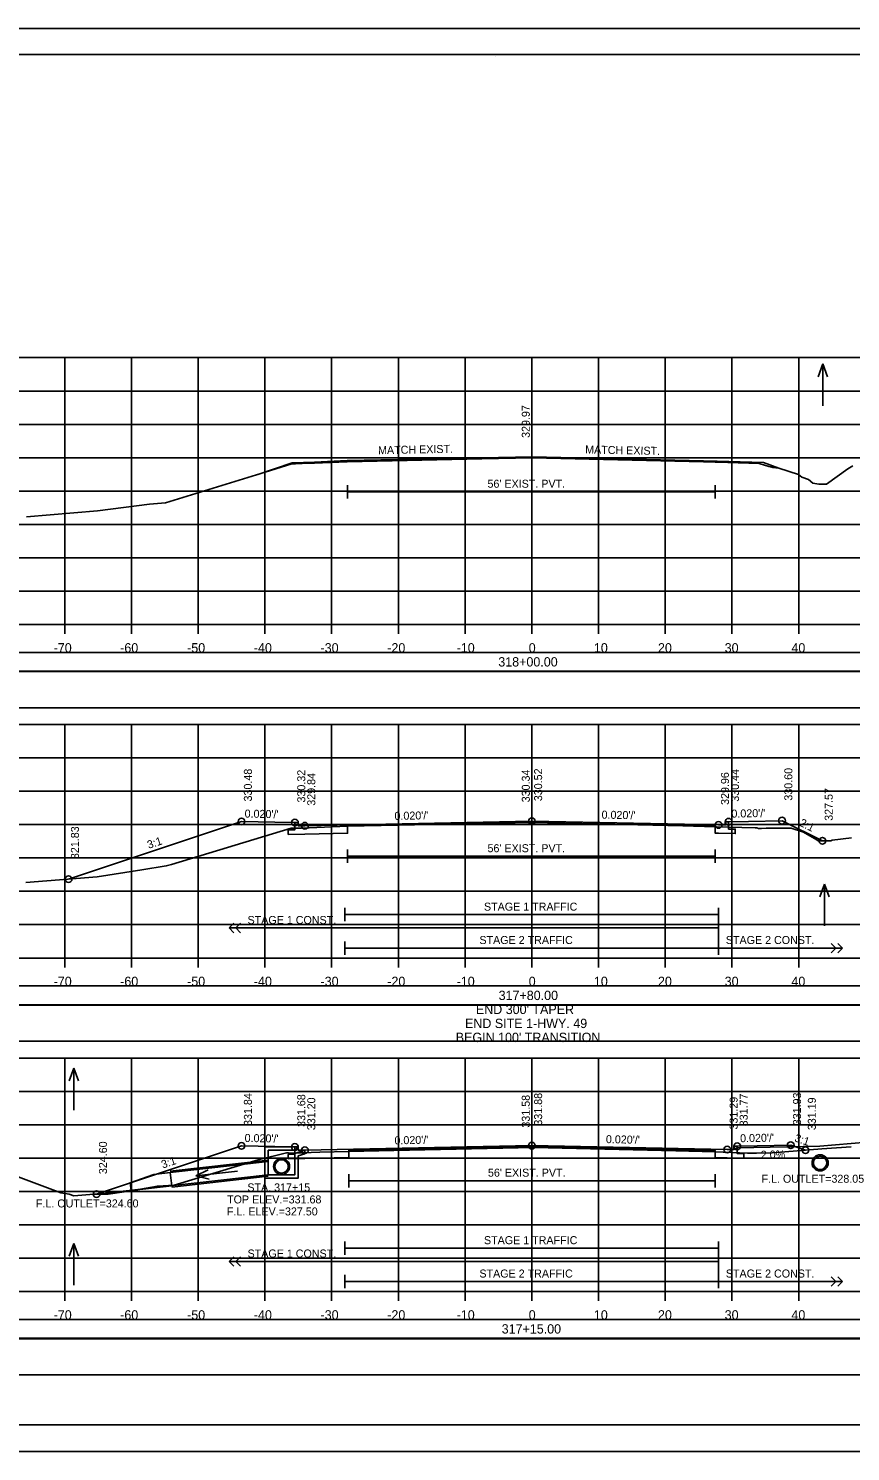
# Model space of a CAD drawing. Extents: x 1368122 to 1710785, y 373130 to 557566.
# Drawn here: x 1369280.1 to 1369403.3, y 375477 to 375690.4 of the extents above; entities that cross this region are included whole.
import ezdxf

# ---------------------------------------------------------------- set-up
doc = ezdxf.new("R2010")
doc.units = 0
for name, color, linetype in [('R_Alt Surface', 7, 'Continuous'), ('R_Axis', 7, 'Continuous'), ('R_Axis Annot', 7, 'Continuous'), ('R_Border', 7, 'Continuous'), ('R_Drive', 7, 'Continuous'), ('R_Exist Surface', 7, 'Continuous'), ('R_Fin Surface', 7, 'Continuous'), ('R_Grid', 7, 'Continuous'), ('R_No Plot', 7, 'Continuous'), ('R_Striping', 7, 'Continuous'), ('R_Water', 7, 'Continuous'), ('R_Water Annot', 7, 'Continuous'), ('R_Xsect Elev', 7, 'Continuous'), ('R_Xsect Slope', 7, 'Continuous')]:
    doc.layers.add(name, color=color, linetype=linetype)

msp = doc.modelspace()

# ---------------------------------------------------------------- linework, layer by layer
for points in [[(1369206.41, 375594.02), (1369504.71, 375594.02), (1369504.71, 375596.84), (1369206.41, 375596.84)], [(1369206.41, 375588.55), (1369504.71, 375588.55), (1369504.71, 375593.96), (1369206.41, 375593.96)], [(1369206.41, 375544.02), (1369504.71, 375544.02), (1369504.71, 375546.84), (1369206.41, 375546.84)], [(1369206.41, 375538.55), (1369504.71, 375538.55), (1369504.71, 375543.96), (1369206.41, 375543.96)], [(1369206.41, 375494.02), (1369504.71, 375494.02), (1369504.71, 375496.84), (1369206.41, 375496.84)], [(1369206.41, 375488.55), (1369504.71, 375488.55), (1369504.71, 375493.96), (1369206.41, 375493.96)]]:
    msp.add_lwpolyline(points, close=True)
at = {"layer": 'R_Alt Surface'}
for points in [[(1369327.95, 375621.93), (1369327.95, 375619.93)], [(1369383.05, 375621.93), (1369383.05, 375619.93)], [(1369327.95, 375620.93), (1369383.05, 375620.93)], [(1369385.06, 375571.46), (1369385.06, 375570.37), (1369386.06, 375570.35), (1369386.06, 375569.68), (1369383.56, 375569.73), (1369383.05, 375569.74), (1369383.05, 375570.82), (1369355.56, 375571.37), (1369327.95, 375570.82), (1369327.95, 375569.74), (1369321.56, 375569.61), (1369319.06, 375569.56), (1369319.06, 375570.23), (1369320.06, 375570.25), (1369320.06, 375571.34)], [(1369327.95, 375567.29), (1369327.95, 375565.29)], [(1369327.95, 375566.29), (1369383.05, 375566.29)], [(1369383.05, 375567.29), (1369383.05, 375565.29)], [(1369386.36, 375522.8), (1369386.36, 375521.71), (1369387.36, 375521.69), (1369387.36, 375521.02), (1369384.86, 375521.07), (1369383.02, 375521.1), (1369383.02, 375522.18), (1369355.56, 375522.73), (1369328.13, 375522.19), (1369328.13, 375521.11), (1369321.56, 375520.97), (1369319.06, 375520.92), (1369319.06, 375521.59), (1369320.06, 375521.61), (1369320.06, 375522.7)], [(1369328.13, 375518.65), (1369328.13, 375516.65)], [(1369328.13, 375517.65), (1369383.02, 375517.65)], [(1369383.02, 375518.65), (1369383.02, 375516.65)]]:
    msp.add_lwpolyline(points, dxfattribs=at)
at = {"layer": 'R_Axis'}
for p, q in [((1369205.56, 375601.03), (1369505.56, 375601.03)), ((1369285.56, 375599.63), (1369285.56, 375601.03)), ((1369295.56, 375599.63), (1369295.56, 375601.03)), ((1369305.56, 375599.63), (1369305.56, 375601.03)), ((1369315.56, 375599.63), (1369315.56, 375601.03)), ((1369325.56, 375599.63), (1369325.56, 375601.03)), ((1369335.56, 375599.63), (1369335.56, 375601.03)), ((1369345.56, 375599.63), (1369345.56, 375601.03)), ((1369355.56, 375599.63), (1369355.56, 375601.03)), ((1369365.56, 375599.63), (1369365.56, 375601.03)), ((1369375.56, 375599.63), (1369375.56, 375601.03)), ((1369385.56, 375599.63), (1369385.56, 375601.03)), ((1369395.56, 375599.63), (1369395.56, 375601.03)), ((1369205.56, 375551.03), (1369505.56, 375551.03)), ((1369285.56, 375549.63), (1369285.56, 375551.03)), ((1369295.56, 375549.63), (1369295.56, 375551.03)), ((1369305.56, 375549.63), (1369305.56, 375551.03)), ((1369315.56, 375549.63), (1369315.56, 375551.03)), ((1369325.56, 375549.63), (1369325.56, 375551.03)), ((1369335.56, 375549.63), (1369335.56, 375551.03)), ((1369345.56, 375549.63), (1369345.56, 375551.03)), ((1369355.56, 375549.63), (1369355.56, 375551.03)), ((1369365.56, 375549.63), (1369365.56, 375551.03)), ((1369375.56, 375549.63), (1369375.56, 375551.03)), ((1369385.56, 375549.63), (1369385.56, 375551.03)), ((1369395.56, 375549.63), (1369395.56, 375551.03)), ((1369205.56, 375501.03), (1369505.56, 375501.03)), ((1369285.56, 375499.63), (1369285.56, 375501.03)), ((1369295.56, 375499.63), (1369295.56, 375501.03)), ((1369305.56, 375499.63), (1369305.56, 375501.03)), ((1369315.56, 375499.63), (1369315.56, 375501.03)), ((1369325.56, 375499.63), (1369325.56, 375501.03)), ((1369335.56, 375499.63), (1369335.56, 375501.03)), ((1369345.56, 375499.63), (1369345.56, 375501.03)), ((1369355.56, 375499.63), (1369355.56, 375501.03)), ((1369365.56, 375499.63), (1369365.56, 375501.03)), ((1369375.56, 375499.63), (1369375.56, 375501.03)), ((1369385.56, 375499.63), (1369385.56, 375501.03)), ((1369395.56, 375499.63), (1369395.56, 375501.03))]:
    msp.add_line(p, q, dxfattribs=at)
at = {"layer": 'R_Border'}
for p, q in [((1369197.56, 375686.49), (1369513.74, 375686.49)), ((1369350.08, 375686.23), (1369350.08, 375686.23)), ((1369350.08, 375686.23), (1369350.08, 375686.23)), ((1369513.74, 375481.03), (1369197.56, 375481.03))]:
    msp.add_line(p, q, dxfattribs=at)
at = {"layer": 'R_Drive'}
for p, q in [((1369415.53, 375524.31), (1369398.74, 375522.8)), ((1369385.86, 375522.3), (1369386.36, 375522.55)), ((1369386.36, 375522.55), (1369398.74, 375522.8))]:
    msp.add_line(p, q, dxfattribs=at)
at = {"layer": 'R_Exist Surface'}
for points in [[(1369279.85, 375617.18), (1369290.45, 375618.07), (1369298.25, 375619.05), (1369300.66, 375619.29), (1369315.6, 375623.88), (1369319.62, 375625.13), (1369320.16, 375625.13), (1369321.14, 375625.14), (1369323, 375625.21), (1369327.91, 375625.42), (1369348.09, 375625.85), (1369355.61, 375626), (1369381.31, 375625.41), (1369383.02, 375625.36), (1369383.33, 375625.36), (1369389.66, 375625.16), (1369391.09, 375624.71), (1369391.33, 375624.64), (1369391.67, 375624.56), (1369392.6, 375624.48), (1369395.55, 375623.53), (1369396.04, 375623.14), (1369397.03, 375622.79), (1369397.69, 375622.23), (1369398.6, 375622.07), (1369399.71, 375622.06), (1369402.94, 375624.36), (1369403.68, 375624.81)], [(1369279.73, 375562.33), (1369290.4, 375563.22), (1369297.13, 375564.25), (1369300.78, 375564.83), (1369301.56, 375565.06), (1369319.52, 375570.52), (1369320.75, 375570.52), (1369321.05, 375570.52), (1369322.21, 375570.57), (1369327.95, 375570.79), (1369351.25, 375571.28), (1369355.69, 375571.37), (1369378.2, 375570.83), (1369383.05, 375570.71), (1369389.04, 375570.56), (1369389.28, 375570.55), (1369389.53, 375570.47), (1369389.64, 375570.46), (1369389.99, 375570.46), (1369390.67, 375570.51), (1369394.44, 375570.49), (1369396.3, 375569.92), (1369398.28, 375568.75), (1369398.46, 375568.61), (1369398.51, 375568.61), (1369400.36, 375568.58), (1369400.58, 375568.68), (1369403.5, 375569.04)], [(1369276.18, 375519.14), (1369284.97, 375515.83), (1369286.24, 375515.61), (1369286.93, 375515.38), (1369289.94, 375515.63), (1369292.05, 375515.61), (1369296.53, 375516.29), (1369296.93, 375516.4), (1369299.46, 375516.84), (1369299.47, 375516.84), (1369301.96, 375516.99), (1369314.55, 375520.78), (1369318.8, 375521.84), (1369319.11, 375521.83), (1369319.9, 375521.79), (1369323.81, 375521.9), (1369328.13, 375522.03), (1369334.87, 375522.17), (1369355.85, 375522.61), (1369377.17, 375522.1), (1369383.02, 375521.96), (1369387.87, 375521.79), (1369389.26, 375521.76), (1369391.6, 375521.82), (1369393.49, 375521.99), (1369399.01, 375522.4), (1369403.42, 375522.73)]]:
    msp.add_lwpolyline(points, dxfattribs=at)
at = {"layer": 'R_Fin Surface'}
for p, q in [((1369319.64, 375625.25), (1369314.49, 375623.54)), ((1369390.3, 375625.31), (1369392.6, 375624.48))]:
    msp.add_line(p, q, dxfattribs=at)
for points in [[(1369319.64, 375625.25), (1369323, 375625.38), (1369327.91, 375625.59), (1369348.09, 375626.02), (1369355.61, 375626.17), (1369381.31, 375625.58), (1369383.02, 375625.53), (1369383.33, 375625.53), (1369390.3, 375625.31)], [(1369286.14, 375562.86), (1369312.06, 375571.5), (1369317.06, 375571.4), (1369320.06, 375571.34), (1369320.56, 375571.34), (1369320.56, 375570.84), (1369321.56, 375570.86), (1369355.56, 375571.54), (1369383.56, 375570.98), (1369384.56, 375570.96), (1369384.56, 375571.46), (1369385.06, 375571.46), (1369388.06, 375571.52), (1369393.06, 375571.62), (1369399.11, 375568.6)], [(1369290.34, 375515.63), (1369312.06, 375522.86), (1369317.06, 375522.76), (1369320.06, 375522.7), (1369320.56, 375522.7), (1369320.56, 375522.2), (1369321.56, 375522.22), (1369355.56, 375522.9), (1369384.86, 375522.32), (1369385.86, 375522.3), (1369385.86, 375522.8), (1369386.36, 375522.8), (1369389.36, 375522.86), (1369394.36, 375522.96), (1369396.58, 375522.22)]]:
    msp.add_lwpolyline(points, dxfattribs=at)
at = {"layer": 'R_Grid'}
for p, q in [((1369205.56, 375641.03), (1369505.56, 375641.03)), ((1369285.56, 375601.03), (1369285.56, 375641.03)), ((1369295.56, 375601.03), (1369295.56, 375641.03)), ((1369305.56, 375601.03), (1369305.56, 375641.03)), ((1369315.56, 375601.03), (1369315.56, 375641.03)), ((1369325.56, 375601.03), (1369325.56, 375641.03)), ((1369335.56, 375601.03), (1369335.56, 375641.03)), ((1369345.56, 375601.03), (1369345.56, 375641.03)), ((1369355.56, 375601.03), (1369355.56, 375641.03)), ((1369365.56, 375601.03), (1369365.56, 375641.03)), ((1369375.56, 375601.03), (1369375.56, 375641.03)), ((1369385.56, 375601.03), (1369385.56, 375641.03)), ((1369395.56, 375601.03), (1369395.56, 375641.03)), ((1369205.56, 375636.03), (1369505.56, 375636.03)), ((1369205.56, 375631.03), (1369505.56, 375631.03)), ((1369205.56, 375626.03), (1369505.56, 375626.03)), ((1369205.56, 375621.03), (1369505.56, 375621.03)), ((1369205.56, 375616.03), (1369505.56, 375616.03)), ((1369205.56, 375611.03), (1369505.56, 375611.03)), ((1369205.56, 375606.03), (1369505.56, 375606.03)), ((1369205.56, 375601.03), (1369505.56, 375601.03)), ((1369205.56, 375586.03), (1369505.56, 375586.03)), ((1369285.56, 375551.03), (1369285.56, 375586.03)), ((1369295.56, 375551.03), (1369295.56, 375586.03)), ((1369305.56, 375551.03), (1369305.56, 375586.03)), ((1369315.56, 375551.03), (1369315.56, 375586.03)), ((1369325.56, 375551.03), (1369325.56, 375586.03)), ((1369335.56, 375551.03), (1369335.56, 375586.03)), ((1369345.56, 375551.03), (1369345.56, 375586.03)), ((1369355.56, 375551.03), (1369355.56, 375586.03)), ((1369365.56, 375551.03), (1369365.56, 375586.03)), ((1369375.56, 375551.03), (1369375.56, 375586.03)), ((1369385.56, 375551.03), (1369385.56, 375586.03)), ((1369395.56, 375551.03), (1369395.56, 375586.03)), ((1369205.56, 375581.03), (1369505.56, 375581.03)), ((1369205.56, 375576.03), (1369505.56, 375576.03)), ((1369205.56, 375571.03), (1369505.56, 375571.03)), ((1369205.56, 375566.03), (1369505.56, 375566.03)), ((1369205.56, 375561.03), (1369505.56, 375561.03)), ((1369205.56, 375556.03), (1369505.56, 375556.03)), ((1369205.56, 375551.03), (1369505.56, 375551.03)), ((1369205.56, 375536.03), (1369505.56, 375536.03)), ((1369285.56, 375501.03), (1369285.56, 375536.03)), ((1369295.56, 375501.03), (1369295.56, 375536.03)), ((1369305.56, 375501.03), (1369305.56, 375536.03)), ((1369315.56, 375501.03), (1369315.56, 375536.03)), ((1369325.56, 375501.03), (1369325.56, 375536.03)), ((1369335.56, 375501.03), (1369335.56, 375536.03)), ((1369345.56, 375501.03), (1369345.56, 375536.03)), ((1369355.56, 375501.03), (1369355.56, 375536.03)), ((1369365.56, 375501.03), (1369365.56, 375536.03)), ((1369375.56, 375501.03), (1369375.56, 375536.03)), ((1369385.56, 375501.03), (1369385.56, 375536.03)), ((1369395.56, 375501.03), (1369395.56, 375536.03)), ((1369205.56, 375531.03), (1369505.56, 375531.03)), ((1369205.56, 375526.03), (1369505.56, 375526.03)), ((1369205.56, 375521.03), (1369505.56, 375521.03)), ((1369205.56, 375516.03), (1369505.56, 375516.03)), ((1369205.56, 375511.03), (1369505.56, 375511.03)), ((1369205.56, 375506.03), (1369505.56, 375506.03)), ((1369205.56, 375501.03), (1369505.56, 375501.03))]:
    msp.add_line(p, q, dxfattribs=at)
at = {"layer": 'R_No Plot'}
for p, q in [((1369185.16, 375690.38), (1369518.49, 375690.38)), ((1369316.06, 375520.74), (1369301.35, 375519.08)), ((1369316.06, 375518.32), (1369301.62, 375516.69)), ((1369185.16, 375477.05), (1369518.49, 375477.05))]:
    msp.add_line(p, q, dxfattribs=at)
for points in [[(1369185.15, 375690.38), (1369518.49, 375690.38), (1369518.49, 375477.04), (1369185.15, 375477.04)], [(1369431.48, 375686.49), (1369451.1, 375686.49), (1369451.1, 375676.61), (1369467.21, 375676.61), (1369490.41, 375676.61), (1369490.53, 375648.45), (1369513.74, 375648.45), (1369513.74, 375481.03), (1369197.56, 375481.03), (1369197.56, 375686.49)]]:
    msp.add_lwpolyline(points, close=True, dxfattribs=at)
for centre, radius in [((1369312.06, 375571.5), 0.5), ((1369320.06, 375571.34), 0.5), ((1369321.56, 375570.86), 0.5), ((1369355.56, 375571.54), 0.5), ((1369383.56, 375570.98), 0.5), ((1369385.06, 375571.46), 0.5), ((1369393.06, 375571.62), 0.5), ((1369399.11, 375568.6), 0.5), ((1369286.14, 375562.86), 0.5), ((1369312.06, 375522.86), 0.5), ((1369355.56, 375522.9), 0.5), ((1369386.36, 375522.8), 0.5), ((1369394.36, 375522.96), 0.5), ((1369320.06, 375522.7), 0.5), ((1369321.56, 375522.22), 0.5), ((1369384.86, 375522.32), 0.5), ((1369396.58, 375522.22), 0.5), ((1369398.77, 375520.32), 1.21), ((1369318.06, 375519.78), 1.21), ((1369290.34, 375515.63), 0.5)]:
    msp.add_circle(centre, radius, dxfattribs=at)
at = {"layer": 'R_Striping'}
for p, q in [((1369310.2, 375555.53), (1369310.91, 375556.23)), ((1369310.91, 375554.82), (1369310.2, 375555.53)), ((1369311.2, 375555.53), (1369311.91, 375556.23)), ((1369311.91, 375554.82), (1369311.2, 375555.53)), ((1369401.11, 375552.53), (1369400.41, 375553.23)), ((1369402.11, 375552.53), (1369401.41, 375553.23)), ((1369402.11, 375552.53), (1369383.56, 375552.53)), ((1369400.41, 375551.82), (1369401.11, 375552.53)), ((1369401.41, 375551.82), (1369402.11, 375552.53)), ((1369310.2, 375505.53), (1369310.91, 375506.23)), ((1369311.2, 375505.53), (1369311.91, 375506.23)), ((1369310.91, 375504.82), (1369310.2, 375505.53)), ((1369311.91, 375504.82), (1369311.2, 375505.53)), ((1369402.11, 375502.53), (1369383.56, 375502.53)), ((1369401.11, 375502.53), (1369400.41, 375503.23)), ((1369400.41, 375501.82), (1369401.11, 375502.53)), ((1369402.11, 375502.53), (1369401.41, 375503.23)), ((1369401.41, 375501.82), (1369402.11, 375502.53))]:
    msp.add_line(p, q, dxfattribs=at)
for points in [[(1369327.56, 375558.53), (1369327.56, 375556.53)], [(1369327.56, 375557.53), (1369383.56, 375557.53)], [(1369383.56, 375558.53), (1369383.56, 375551.53)], [(1369383.56, 375555.53), (1369310.2, 375555.53)], [(1369327.56, 375553.53), (1369327.56, 375551.53)], [(1369327.56, 375552.53), (1369383.56, 375552.53)], [(1369327.56, 375508.53), (1369327.56, 375506.53)], [(1369383.56, 375508.53), (1369383.56, 375501.53)], [(1369327.56, 375507.53), (1369383.56, 375507.53)], [(1369383.56, 375505.53), (1369310.2, 375505.53)], [(1369327.56, 375503.53), (1369327.56, 375501.53)], [(1369327.56, 375502.53), (1369383.56, 375502.53)]]:
    msp.add_lwpolyline(points, dxfattribs=at)
at = {"layer": 'R_Water'}
for p, q in [((1369315.56, 375522.7), (1369320.31, 375522.7)), ((1369315.56, 375521.2), (1369315.56, 375522.7)), ((1369316.06, 375521.2), (1369316.06, 375522.2)), ((1369316.06, 375522.2), (1369320.06, 375522.2)), ((1369320.39, 375522.54), (1369320.06, 375522.2)), ((1369321.56, 375522.22), (1369320.06, 375521.7)), ((1369320.06, 375521.2), (1369320.06, 375521.7)), ((1369320.39, 375522.54), (1369320.31, 375522.7)), ((1369321.56, 375521.69), (1369320.56, 375521.35)), ((1369320.56, 375521.2), (1369320.56, 375521.35)), ((1369316.06, 375520.53), (1369301.38, 375518.87)), ((1369316.06, 375518.53), (1369290.34, 375515.63))]:
    msp.add_line(p, q, dxfattribs=at)
for points in [[(1369320.56, 375521.2), (1369320.56, 375518.03), (1369318.06, 375518.03), (1369315.56, 375518.03), (1369315.56, 375521.2)], [(1369320.06, 375521.2), (1369320.06, 375518.53), (1369318.06, 375518.53), (1369316.06, 375518.53), (1369316.06, 375521.2)], [(1369321.56, 375521.69), (1369321.56, 375522.22)]]:
    msp.add_lwpolyline(points, dxfattribs=at)
msp.add_lwpolyline([(1369301.38, 375518.87), (1369301.6, 375516.88), (1369295.52, 375516.2), (1369295.39, 375517.31), (1369298.89, 375518.59)], close=True, dxfattribs=at)
for centre in [(1369398.77, 375520.32), (1369318.06, 375519.78)]:
    msp.add_circle(centre, 1, dxfattribs=at)
at = {"layer": 'R_Water Annot'}
for p, q in [((1369399.16, 375640.09), (1369398.46, 375638.17)), ((1369399.16, 375633.81), (1369399.16, 375640.09)), ((1369399.16, 375640.09), (1369399.86, 375638.17)), ((1369399.44, 375562.12), (1369398.74, 375560.19)), ((1369399.44, 375555.83), (1369399.44, 375562.12)), ((1369399.44, 375562.12), (1369400.14, 375560.19)), ((1369286.93, 375534.52), (1369286.23, 375532.6)), ((1369286.93, 375528.24), (1369286.93, 375534.52)), ((1369286.93, 375534.52), (1369287.63, 375532.6)), ((1369305.22, 375518.36), (1369307.06, 375519.27)), ((1369311.47, 375519.06), (1369305.22, 375518.36)), ((1369305.22, 375518.36), (1369307.21, 375517.88)), ((1369286.93, 375508.25), (1369286.23, 375506.33)), ((1369286.93, 375501.97), (1369286.93, 375508.25)), ((1369286.93, 375508.25), (1369287.63, 375506.33))]:
    msp.add_line(p, q, dxfattribs=at)
at = {"layer": 'R_Xsect Elev'}
for p, q in [((1369355.56, 375626), (1369355.56, 375636)), ((1369355.56, 375571.37), (1369355.56, 375581.37)), ((1369355.56, 375522.6), (1369355.56, 375532.6))]:
    msp.add_line(p, q, dxfattribs=at)

# ---------------------------------------------------------------- texts
at = {"layer": 'R_Axis Annot'}
for s, p in [('-70', (1369283.9, 375596.83)), ('-60', (1369293.87, 375596.83)), ('-50', (1369303.9, 375596.83)), ('-40', (1369313.9, 375596.83)), ('-30', (1369323.9, 375596.83)), ('-20', (1369333.9, 375596.83)), ('-10', (1369344.3, 375596.83)), ('0', (1369355.1, 375596.83)), ('10', (1369364.87, 375596.83)), ('20', (1369374.47, 375596.83)), ('30', (1369384.47, 375596.83)), ('40', (1369394.47, 375596.83)), ('318+00.00', (1369350.54, 375594.73)), ('-70', (1369283.9, 375546.83)), ('-60', (1369293.87, 375546.83)), ('-50', (1369303.9, 375546.83)), ('-40', (1369313.9, 375546.83)), ('-30', (1369323.9, 375546.83)), ('-20', (1369333.9, 375546.83)), ('-10', (1369344.3, 375546.83)), ('0', (1369355.1, 375546.83)), ('10', (1369364.87, 375546.83)), ('20', (1369374.47, 375546.83)), ('30', (1369384.47, 375546.83)), ('40', (1369394.47, 375546.83)), ('317+80.00', (1369350.59, 375544.73)), ("END 300' TAPER", (1369347.18, 375542.63)), ('END SITE 1-HWY. 49', (1369345.55, 375540.53)), ("BEGIN 100' TRANSITION", (1369344.16, 375538.43)), ('-70', (1369283.9, 375496.83)), ('-60', (1369293.87, 375496.83)), ('-50', (1369303.9, 375496.83)), ('-40', (1369313.9, 375496.83)), ('-30', (1369323.9, 375496.83)), ('-20', (1369333.9, 375496.83)), ('-10', (1369344.3, 375496.83)), ('0', (1369355.1, 375496.83)), ('10', (1369364.87, 375496.83)), ('20', (1369374.47, 375496.83)), ('30', (1369384.47, 375496.83)), ('40', (1369394.47, 375496.83)), ('317+15.00', (1369351.05, 375494.73))]:
    msp.add_text(s, height=1.4, dxfattribs=at).set_placement(p)
at = {"layer": 'R_Striping'}
for s, p in [('STAGE 1 TRAFFIC', (1369348.39, 375558.13)), ('STAGE 1 CONST.', (1369312.96, 375556.13)), ('STAGE 2 TRAFFIC', (1369347.71, 375553.13)), ('STAGE 2 CONST.', (1369384.64, 375553.13)), ('STAGE 1 TRAFFIC', (1369348.39, 375508.13)), ('STAGE 1 CONST.', (1369312.96, 375506.13)), ('STAGE 2 TRAFFIC', (1369347.71, 375503.13)), ('STAGE 2 CONST.', (1369384.64, 375503.13))]:
    msp.add_text(s, height=1.2, dxfattribs=at).set_placement(p)
at = {"layer": 'R_Water'}
for p in [(1369348.92, 375621.53), (1369348.92, 375566.89), (1369348.99, 375518.25)]:
    msp.add_text("56' EXIST. PVT.", height=1.2, dxfattribs=at).set_placement(p)
at = {"layer": 'R_Water Annot'}
for s, p in [('STA. 317+15', (1369312.93, 375516.04)), ('F.L. OUTLET=328.05', (1369389.99, 375517.34)), ('F.L. OUTLET=324.60', (1369281.24, 375513.64)), ('TOP ELEV.=331.68', (1369309.89, 375514.24)), ('F.L. ELEV.=327.50', (1369309.87, 375512.44))]:
    msp.add_text(s, height=1.2, dxfattribs=at).set_placement(p)
at = {"layer": 'R_Xsect Elev'}
for s, rotation, p in [('329.97', 90, (1369355.26, 375629)), ('330.48', 90, (1369313.61, 375574.5)), ('330.32', 90, (1369321.61, 375574.34)), ('329.84', 90, (1369323.11, 375573.86)), ('330.34', 90, (1369355.26, 375574.37)), ('330.52', 90, (1369357.11, 375574.54)), ('329.96', 90, (1369385.11, 375573.98)), ('330.44', 90, (1369386.61, 375574.46)), ('330.60', 90, (1369394.61, 375574.62)), ('327.57', 90, (1369400.66, 375571.6)), ('321.83', 90, (1369287.69, 375565.86)), ('331.84', 90, (1369313.61, 375525.86)), ('331.68', 90, (1369321.61, 375525.7)), ('331.20', 90, (1369323.11, 375525.22)), ('331.58', 90, (1369355.26, 375525.6)), ('331.88', 90, (1369357.11, 375525.9)), ('331.29', 90, (1369386.41, 375525.32)), ('331.77', 90, (1369387.91, 375525.8)), ('331.93', 90, (1369395.91, 375525.96)), ('331.19', 90, (1369398.13, 375525.22)), ('324.60', 90, (1369291.89, 375518.63)), ('2.0%', 1.1458, (1369389.89, 375520.93))]:
    msp.add_text(s, height=1.2, rotation=rotation, dxfattribs=at).set_placement(p)
at = {"layer": 'R_Xsect Slope'}
for s, rotation, p in [('MATCH EXIST.', 1.1458, (1369332.53, 375626.55)), ('MATCH EXIST.', 358.8542, (1369363.55, 375626.67)), ("0.020'/'", 358.8542, (1369312.51, 375572.09)), ("0.020'/'", 1.1458, (1369334.99, 375571.73)), ("0.020'/'", 358.8542, (1369366.01, 375571.93)), ("0.020'/'", 1.1458, (1369385.49, 375572.07)), ('2:1', 333.4357, (1369395.56, 375570.93)), ('3:1', 18.4349, (1369298.15, 375567.39)), ("0.020'/'", 358.8542, (1369312.51, 375523.46)), ("0.020'/'", 1.1458, (1369334.99, 375523.09)), ("0.020'/'", 358.8542, (1369366.66, 375523.28)), ("0.020'/'", 1.1458, (1369386.79, 375523.41)), ('3:1', 341.5651, (1369394.84, 375523.57)), ('3:1', 18.4349, (1369300.26, 375519.46))]:
    msp.add_text(s, height=1.2, rotation=rotation, dxfattribs=at).set_placement(p)

doc.saveas('drawing.dxf')
